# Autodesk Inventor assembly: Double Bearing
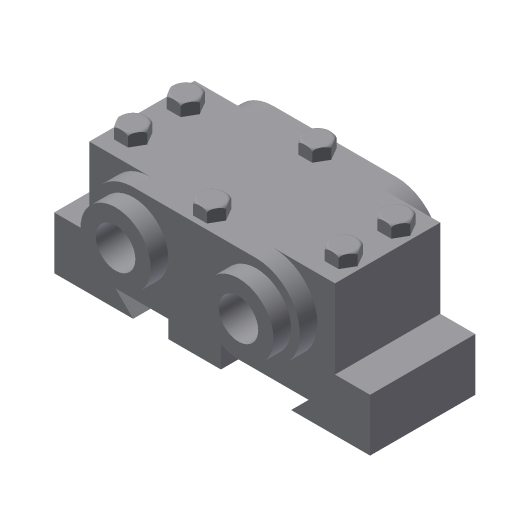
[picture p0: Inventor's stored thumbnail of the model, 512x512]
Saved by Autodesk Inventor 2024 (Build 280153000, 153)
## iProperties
Shininess: 64.0
Length Units: 11269
Angle Units: 11279
Time Units: 11290
Mass Units: 11283
Length Display Precision: 3
Angle Display Precision: 2
Created: 2002-02
Part Number: Double Bearing
Document SubType Name: Assembly
Designer: ***
Density: 0.0
Volumn: 0.0
Area: 0.0
PropertySet Name: Model Information
Control State: 0
Master: False
Checked Out: False
Author: ***
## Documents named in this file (5)
- D:\PROJECTS\Project 2023\RESOURCES INVENTOR 2024\RESOURCES INVENTOR 2024\Inventor_2024_tut\Inventor_2024_tut\c12_Inv_2024_tut\c12_Inv_tut_2024\c12_tut02_inv\Double Bearing.iam
- D:\PROJECTS\Project 2023\RESOURCES INVENTOR 2024\RESOURCES INVENTOR 2024\Inventor_2024_tut\Inventor_2024_tut\c12_Inv_2024_tut\c12_Inv_tut_2024\c12_tut02_inv\Base.ipt
- D:\PROJECTS\Project 2023\RESOURCES INVENTOR 2024\RESOURCES INVENTOR 2024\Inventor_2024_tut\Inventor_2024_tut\c12_Inv_2024_tut\c12_Inv_tut_2024\c12_tut02_inv\Cap.ipt
- D:\PROJECTS\Project 2023\RESOURCES INVENTOR 2024\RESOURCES INVENTOR 2024\Inventor_2024_tut\Inventor_2024_tut\c12_Inv_2024_tut\c12_Inv_tut_2024\c12_tut02_inv\Bushing.ipt
- D:\PROJECTS\Project 2023\RESOURCES INVENTOR 2024\RESOURCES INVENTOR 2024\Inventor_2024_tut\Inventor_2024_tut\c12_Inv_2024_tut\c12_Inv_tut_2024\c12_tut02_inv\Bolt.ipt
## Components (10 placed, 4 different names)
1. Base:1 — Insert:1, Insert:2
2. Cap:1 — Insert:1, Insert:2, Insert:3, Insert:4, Insert:5, Insert:6
3. Bushing:1 — Insert:3
4. Bushing:2 — Insert:4
5. Bolt:1 — Insert:5
6. Bolt:6
7. Bolt:7
8. Bolt:8
9. Bolt:5 — Insert:6
10. Bolt:9
## Component patterns: Component Pattern 1 (4 elements), Component Pattern 2 (2 elements)
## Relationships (6: Insert 6)
- Insert:1: Base:1 ↔ Cap:1
- Insert:2: Base:1 ↔ Cap:1
- Insert:3: Cap:1 ↔ Bushing:1
- Insert:4: Cap:1 ↔ Bushing:2
- Insert:5: Cap:1 ↔ Bolt:1
- Insert:6: Cap:1 ↔ Bolt:5
